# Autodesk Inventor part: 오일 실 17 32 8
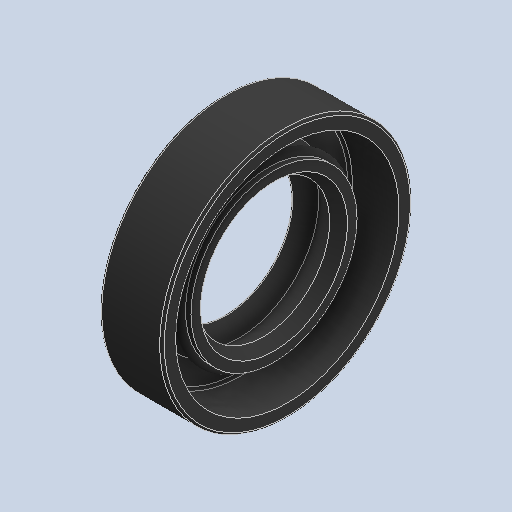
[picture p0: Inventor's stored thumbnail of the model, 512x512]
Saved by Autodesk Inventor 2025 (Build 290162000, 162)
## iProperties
Created: 2026-07
Part Number: 오일 실 17 32 8
Material: 고무
Description: 오일-실
Document SubType Name: Modeling
Designer: KDI
Density: 0.93 g/cm^3
Appearance: 기본값
Author: jhkim
Revision Number: 1
Sending System: Autodesk Inventor 2027
Preprocessor: ST-DEVELOPER v20.1
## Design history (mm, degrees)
feature "Solid1"
node "솔리드1"
